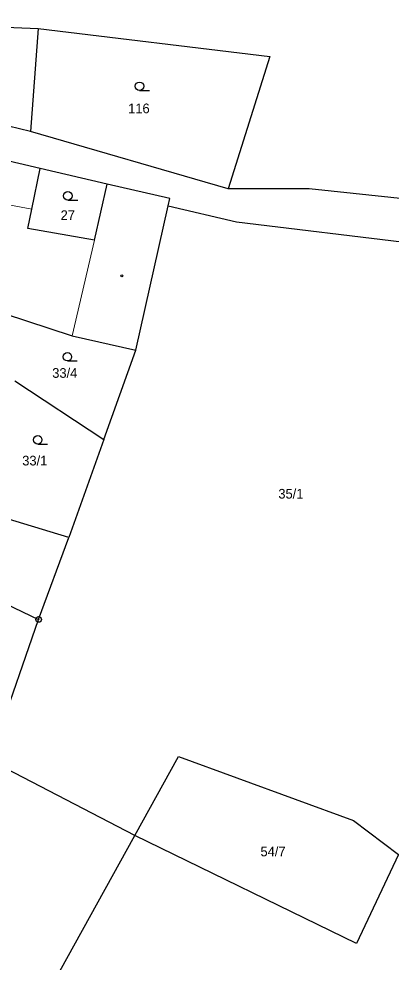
# Model space of a CAD drawing. Extents: x -791548 to -789311, y -1142631 to -1140855.
# Drawn here: x -790206 to -790140.3, y -1142288.4 to -1142122.1 of the extents above; entities that cross this region are included whole.
import ezdxf
from ezdxf.enums import TextEntityAlignment as Align

# ---------------------------------------------------------------- set-up
doc = ezdxf.new("R2010")
doc.units = 0
doc.header["$LTSCALE"] = 0.68
for name, color, linetype, lineweight in [('1', 7, 'Continuous', 25), ('3', 7, 'Continuous', 25), ('4', 7, 'Continuous', 13), ('5', 7, 'Continuous', 25), ('8', 7, 'Continuous', 25)]:
    doc.layers.add(name, color=color, linetype=linetype, lineweight=lineweight)
doc.layers.add('2', color=7, linetype='Continuous')

msp = doc.modelspace()

# ---------------------------------------------------------------- linework, layer by layer
at = {"layer": '1'}
for p, q in [((-790248.33, -1142122.09), (-790202.6, -1142123.76)), ((-790202.6, -1142123.76), (-790203.93, -1142141.96)), ((-790202.6, -1142123.76), (-790161.76, -1142128.7)), ((-790161.76, -1142128.7), (-790169.07, -1142152.05)), ((-790203.93, -1142141.96), (-790247.24, -1142131.35)), ((-790202.22, -1142148.44), (-790248.37, -1142137.71)), ((-790169.07, -1142152.05), (-790203.93, -1142141.96)), ((-790203.71, -1142155.65), (-790202.22, -1142148.44)), ((-790190.39, -1142151.21), (-790202.22, -1142148.44)), ((-790192.67, -1142161.1), (-790190.39, -1142151.21)), ((-790179.34, -1142153.74), (-790190.39, -1142151.21)), ((-790154.8, -1142152.05), (-790169.07, -1142152.05)), ((-790128.15, -1142154.89), (-790154.8, -1142152.05)), ((-790179.64, -1142155.07), (-790179.34, -1142153.74)), ((-790204.42, -1142159.05), (-790203.71, -1142155.65)), ((-790185.34, -1142180.47), (-790179.64, -1142155.07)), ((-790179.64, -1142155.07), (-790167.62, -1142157.89)), ((-790167.62, -1142157.89), (-790126.91, -1142162.79)), ((-790192.67, -1142161.1), (-790204.42, -1142159.05)), ((-790208.6, -1142174.01), (-790196.56, -1142177.95)), ((-790196.56, -1142177.95), (-790185.34, -1142180.47)), ((-790191, -1142196.24), (-790185.34, -1142180.47)), ((-790206.67, -1142185.87), (-790191, -1142196.24)), ((-790191, -1142196.24), (-790197.2, -1142213.53)), ((-790197.2, -1142213.53), (-790220.5, -1142206.42)), ((-790202.5, -1142227.96), (-790197.2, -1142213.53)), ((-790225.57, -1142217.02), (-790202.5, -1142227.96)), ((-790211.14, -1142252.78), (-790202.5, -1142227.96)), ((-790185.55, -1142266.07), (-790177.81, -1142252.11)), ((-790177.81, -1142252.11), (-790146.97, -1142263.43)), ((-790185.55, -1142266.07), (-790211.14, -1142252.78)), ((-790146.97, -1142263.43), (-790139.03, -1142269.41)), ((-790203.27, -1142298.05), (-790185.55, -1142266.07)), ((-790146.45, -1142285.1), (-790185.55, -1142266.07)), ((-790139.03, -1142269.41), (-790146.45, -1142285.1))]:
    msp.add_line(p, q, dxfattribs=at)
at = {"layer": '3'}
for p, q in [((-790184.713, -1142134.73), (-790182.963, -1142134.73)), ((-790197.353, -1142154.05), (-790195.603, -1142154.05)), ((-790197.433, -1142182.39), (-790195.683, -1142182.39)), ((-790202.663, -1142197.04), (-790200.913, -1142197.04))]:
    msp.add_line(p, q, dxfattribs=at)
for centre in [(-790184.7129, -1142133.9798), (-790197.3529, -1142153.2998), (-790197.4329, -1142181.6398), (-790202.6629, -1142196.2898)]:
    msp.add_circle(centre, 0.75, dxfattribs=at)
at = {"layer": '4'}
for p, q in [((-790250.07, -1142146.94), (-790203.71, -1142155.65)), ((-790196.56, -1142177.95), (-790192.67, -1142161.1))]:
    msp.add_line(p, q, dxfattribs=at)
at = {"layer": '5'}
msp.add_circle((-790187.8488, -1142167.3933), 0.175, dxfattribs=at)
at = {"layer": '8'}
for radius in [0.5, 0.0303]:
    msp.add_circle((-790202.5, -1142227.9599), radius, dxfattribs=at)

# ---------------------------------------------------------------- texts
at = {"layer": '2'}
for s, p in [('116', (-790184.819, -1142138.722)), ('27', (-790197.359, -1142157.542)), ('33/4', (-790197.889, -1142185.365)), ('33/1', (-790203.179, -1142200.812)), ('35/1', (-790158.019, -1142206.652)), ('54/7', (-790161.169, -1142269.722))]:
    msp.add_text(s, height=1.7, dxfattribs=at).set_placement(p, align=Align.CENTER)

doc.saveas('drawing.dxf')
